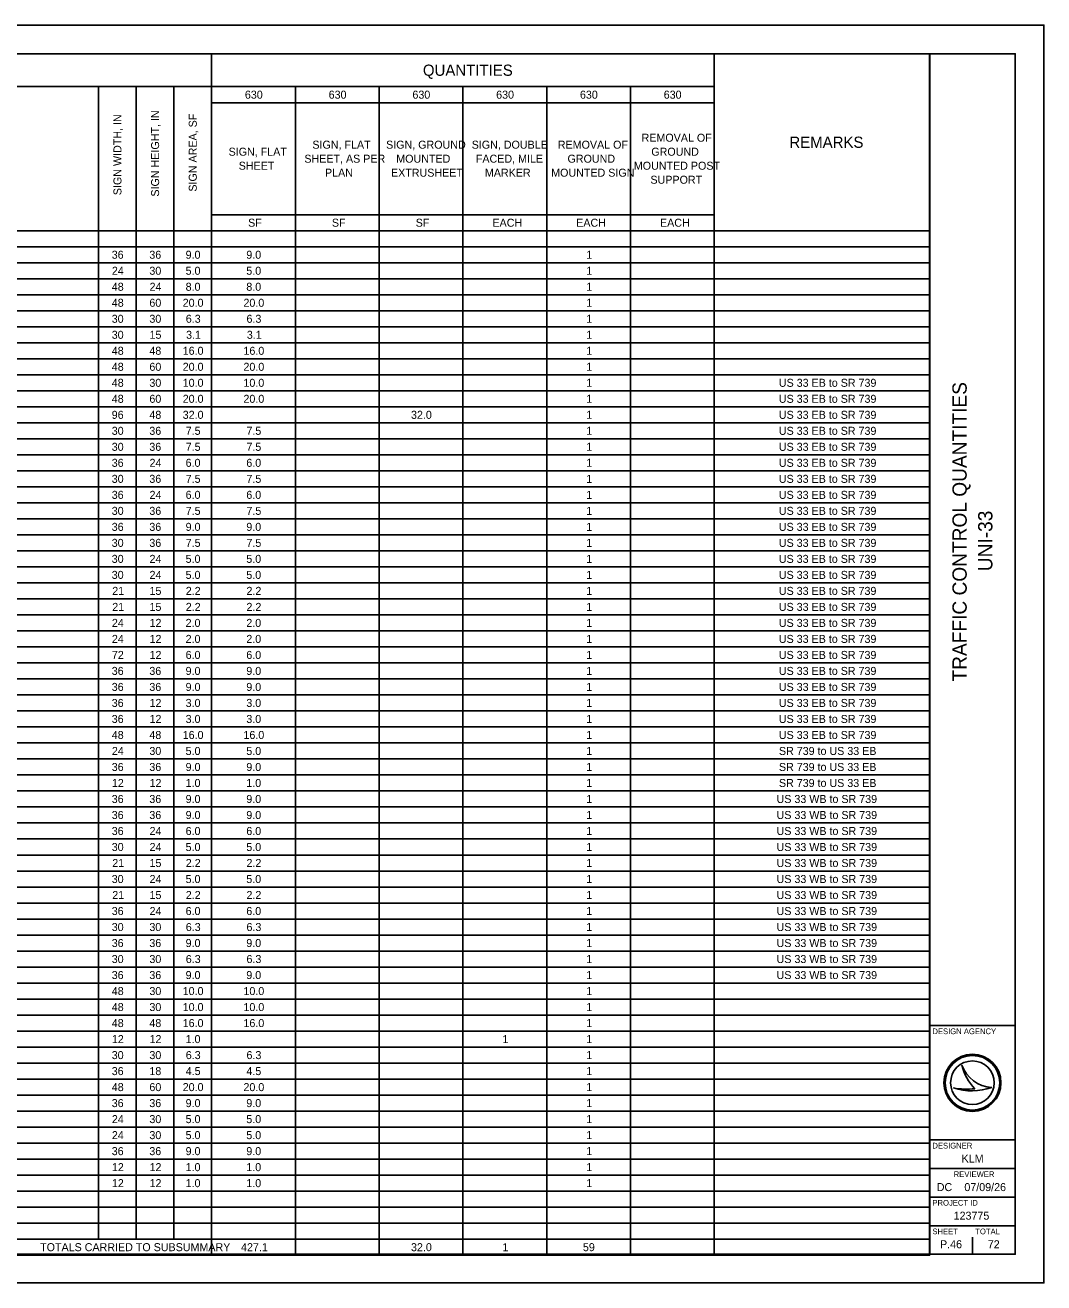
# Model space of a CAD drawing. Extents: x 0 to 34, y 0 to 22.
# Drawn here: x 16.17 to 34, y 0 to 22 of the extents above; entities that cross this region are included whole.
import ezdxf

# ---------------------------------------------------------------- set-up
doc = ezdxf.new("R2010")
doc.units = 0
for name, color, linetype in [('Default', 7, 'Continuous'), ('SH_Border', 7, 'Continuous'), ('SH_Cut_Line', 7, 'Continuous'), ('SH_Data', 7, 'Continuous')]:
    doc.layers.add(name, color=color, linetype=linetype)

msp = doc.modelspace()

# ---------------------------------------------------------------- linework, layer by layer
at = {"layer": 'SH_Border'}
for p, q in [((32, 0.5), (32, 21.5)), ((32, 4.5), (33.5, 4.5)), ((32, 2.5), (33.5, 2.5)), ((32, 2), (33.5, 2)), ((32, 1.5), (33.5, 1.5)), ((32, 1), (33.5, 1))]:
    msp.add_line(p, q, dxfattribs=at)
msp.add_lwpolyline([(1.5, 21.5), (33.5, 21.5), (33.5, 0.5), (1.5, 0.5)], close=True, dxfattribs=at)
at = {"layer": 'SH_Cut_Line'}
msp.add_lwpolyline([(0, 0), (34, 0), (34, 22), (0, 22)], close=True, dxfattribs=at)
at = {"layer": 'SH_Data'}
for p, q in [((1.5, 21.5), (32.004, 21.5)), ((19.436, 21.5), (19.436, 0.484)), ((28.232, 21.5), (28.232, 0.484)), ((32.004, 21.5), (32.004, 0.484)), ((1.5, 20.924), (28.232, 20.924)), ((17.46, 20.924), (17.46, 0.764)), ((18.119, 20.924), (18.119, 0.764)), ((18.778, 20.924), (18.778, 0.764)), ((20.902, 20.924), (20.902, 0.484)), ((22.368, 20.924), (22.368, 0.484)), ((23.834, 20.924), (23.834, 0.484)), ((25.3, 20.924), (25.3, 0.484)), ((26.766, 20.924), (26.766, 0.484)), ((19.436, 20.644), (28.232, 20.644)), ((19.436, 18.684), (28.232, 18.684)), ((1.5, 18.404), (32.004, 18.404)), ((1.5, 18.124), (32.004, 18.124)), ((1.5, 17.844), (32.004, 17.844)), ((1.5, 17.564), (32.004, 17.564)), ((1.5, 17.284), (32.004, 17.284)), ((1.5, 17.004), (32.004, 17.004)), ((1.5, 16.724), (32.004, 16.724)), ((1.5, 16.444), (32.004, 16.444)), ((1.5, 16.164), (32.004, 16.164)), ((1.5, 15.884), (32.004, 15.884)), ((1.5, 15.604), (32.004, 15.604)), ((1.5, 15.324), (32.004, 15.324)), ((1.5, 15.044), (32.004, 15.044)), ((1.5, 14.764), (32.004, 14.764)), ((1.5, 14.484), (32.004, 14.484)), ((1.5, 14.204), (32.004, 14.204)), ((1.5, 13.924), (32.004, 13.924)), ((1.5, 13.644), (32.004, 13.644)), ((1.5, 13.364), (32.004, 13.364)), ((1.5, 13.084), (32.004, 13.084)), ((1.5, 12.804), (32.004, 12.804)), ((1.5, 12.524), (32.004, 12.524)), ((1.5, 12.244), (32.004, 12.244)), ((1.5, 11.964), (32.004, 11.964)), ((1.5, 11.684), (32.004, 11.684)), ((1.5, 11.404), (32.004, 11.404)), ((1.5, 11.124), (32.004, 11.124)), ((1.5, 10.844), (32.004, 10.844)), ((1.5, 10.564), (32.004, 10.564)), ((1.5, 10.284), (32.004, 10.284)), ((1.5, 10.004), (32.004, 10.004)), ((1.5, 9.724), (32.004, 9.724)), ((1.5, 9.444), (32.004, 9.444)), ((1.5, 9.164), (32.004, 9.164)), ((1.5, 8.884), (32.004, 8.884)), ((1.5, 8.604), (32.004, 8.604)), ((1.5, 8.324), (32.004, 8.324)), ((1.5, 8.044), (32.004, 8.044)), ((1.5, 7.764), (32.004, 7.764)), ((1.5, 7.484), (32.004, 7.484)), ((1.5, 7.204), (32.004, 7.204)), ((1.5, 6.924), (32.004, 6.924)), ((1.5, 6.644), (32.004, 6.644)), ((1.5, 6.364), (32.004, 6.364)), ((1.5, 6.084), (32.004, 6.084)), ((1.5, 5.804), (32.004, 5.804)), ((1.5, 5.524), (32.004, 5.524)), ((1.5, 5.244), (32.004, 5.244)), ((1.5, 4.964), (32.004, 4.964)), ((1.5, 4.684), (32.004, 4.684)), ((1.5, 4.404), (32.004, 4.404)), ((1.5, 4.124), (32.004, 4.124)), ((1.5, 3.844), (32.004, 3.844)), ((32.567, 3.81), (32.567, 3.81)), ((1.5, 3.564), (32.004, 3.564)), ((32.417, 3.41), (32.417, 3.41)), ((32.75, 3.5), (32.75, 3.5)), ((33.087, 3.419), (33.087, 3.419)), ((1.5, 3.284), (32.004, 3.284)), ((1.5, 3.004), (32.004, 3.004)), ((1.5, 2.724), (32.004, 2.724)), ((1.5, 2.444), (32.004, 2.444)), ((1.5, 2.164), (32.004, 2.164)), ((1.5, 1.884), (32.004, 1.884)), ((1.5, 1.604), (32.004, 1.604)), ((1.5, 1.324), (32.004, 1.324)), ((1.5, 1.044), (32.004, 1.044)), ((1.5, 0.764), (32.004, 0.764)), ((32.375, 0.675), (32.375, 0.675)), ((32.75, 0.5), (32.75, 0.8)), ((1.5, 0.484), (32.004, 0.484))]:
    msp.add_line(p, q, dxfattribs=at)
for radius in [0.5, 0.477, 0.477, 0.382]:
    msp.add_circle((32.75, 3.5), radius, dxfattribs=at)
for centre, radius, start, end in [((33.116, 3.998), 0.58, 198.9257, 198.9319), ((33.347, 3.97), 0.796, 191.6379, 191.6421), ((33.116, 3.998), 0.58, 198.9319, 267.1657), ((33.347, 3.97), 0.796, 191.6421, 226.0947), ((32.739, 4.37), 1.013, 251.4576, 290.0832), ((32.648, 4.654), 1.266, 259.4964, 259.4995), ((32.739, 4.37), 1.013, 251.4527, 251.4576), ((32.648, 4.654), 1.266, 259.4995, 276.6672)]:
    msp.add_arc(centre, radius, start, end, dxfattribs=at)

# ---------------------------------------------------------------- texts
at = {"layer": 'Default'}
for s, height, p in [('QUANTITIES', 0.196, (23.134, 21.114)), ('630', 0.14, (20.019, 20.714)), ('630', 0.14, (21.485, 20.714)), ('630', 0.14, (22.951, 20.714)), ('630', 0.14, (24.416, 20.714)), ('630', 0.14, (25.882, 20.714)), ('630', 0.14, (27.348, 20.714)), ('REMOVAL OF ', 0.14, (26.961, 19.961)), ('REMARKS', 0.196, (29.547, 19.854)), ('SIGN, FLAT ', 0.14, (19.734, 19.716)), ('SIGN, FLAT ', 0.14, (21.2, 19.839)), ('SIGN, GROUND ', 0.14, (22.49, 19.839)), ('SIGN, DOUBLE ', 0.14, (23.988, 19.839)), ('REMOVAL OF ', 0.14, (25.495, 19.839)), ('GROUND ', 0.14, (27.131, 19.716)), ('SHEET', 0.14, (19.911, 19.471)), ('SHEET, AS PER ', 0.14, (21.06, 19.594)), ('MOUNTED ', 0.14, (22.668, 19.594)), ('FACED, MILE ', 0.14, (24.061, 19.594)), ('GROUND ', 0.14, (25.665, 19.594)), ('MOUNTED POST ', 0.14, (26.825, 19.471)), ('PLAN', 0.14, (21.421, 19.349)), ('EXTRUSHEET', 0.14, (22.576, 19.349)), ('MARKER', 0.14, (24.219, 19.349)), ('MOUNTED SIGN', 0.14, (25.379, 19.349)), ('SUPPORT', 0.14, (27.116, 19.226)), ('SF', 0.14, (20.076, 18.474)), ('SF', 0.14, (21.542, 18.474)), ('SF', 0.14, (23.008, 18.474)), ('EACH', 0.14, (24.351, 18.474)), ('EACH', 0.14, (25.817, 18.474)), ('EACH', 0.14, (27.283, 18.474)), ('36', 0.14, (17.689, 17.914)), ('36', 0.14, (18.347, 17.914)), ('9.0', 0.14, (18.982, 17.914)), ('9.0', 0.14, (20.044, 17.914)), ('1', 0.14, (25.992, 17.914)), ('24', 0.14, (17.692, 17.634)), ('30', 0.14, (18.348, 17.634)), ('5.0', 0.14, (18.982, 17.634)), ('5.0', 0.14, (20.044, 17.634)), ('1', 0.14, (25.992, 17.634)), ('48', 0.14, (17.69, 17.354)), ('24', 0.14, (18.351, 17.354)), ('8.0', 0.14, (18.982, 17.354)), ('8.0', 0.14, (20.044, 17.354)), ('1', 0.14, (25.992, 17.354)), ('48', 0.14, (17.69, 17.074)), ('60', 0.14, (18.348, 17.074)), ('20.0', 0.14, (18.931, 17.074)), ('20.0', 0.14, (19.994, 17.074)), ('1', 0.14, (25.992, 17.074)), ('30', 0.14, (17.689, 16.794)), ('30', 0.14, (18.348, 16.794)), ('6.3', 0.14, (18.985, 16.794)), ('6.3', 0.14, (20.047, 16.794)), ('1', 0.14, (25.992, 16.794)), ('30', 0.14, (17.689, 16.514)), ('15', 0.14, (18.35, 16.514)), ('3.1', 0.14, (18.99, 16.514)), ('3.1', 0.14, (20.053, 16.514)), ('1', 0.14, (25.992, 16.514)), ('48', 0.14, (17.69, 16.234)), ('48', 0.14, (18.348, 16.234)), ('16.0', 0.14, (18.931, 16.234)), ('16.0', 0.14, (19.994, 16.234)), ('1', 0.14, (25.992, 16.234)), ('48', 0.14, (17.69, 15.954)), ('60', 0.14, (18.348, 15.954)), ('20.0', 0.14, (18.931, 15.954)), ('20.0', 0.14, (19.994, 15.954)), ('1', 0.14, (25.992, 15.954)), ('48', 0.14, (17.69, 15.674)), ('30', 0.14, (18.348, 15.674)), ('10.0', 0.14, (18.931, 15.674)), ('10.0', 0.14, (19.994, 15.674)), ('1', 0.14, (25.992, 15.674)), ('US 33 EB to SR 739', 0.14, (29.363, 15.674)), ('48', 0.14, (17.69, 15.394)), ('60', 0.14, (18.348, 15.394)), ('20.0', 0.14, (18.931, 15.394)), ('20.0', 0.14, (19.994, 15.394)), ('1', 0.14, (25.992, 15.394)), ('US 33 EB to SR 739', 0.14, (29.363, 15.394)), ('96', 0.14, (17.689, 15.114)), ('48', 0.14, (18.348, 15.114)), ('32.0', 0.14, (18.931, 15.114)), ('32.0', 0.14, (22.926, 15.114)), ('1', 0.14, (25.992, 15.114)), ('US 33 EB to SR 739', 0.14, (29.363, 15.114)), ('30', 0.14, (17.689, 14.834)), ('36', 0.14, (18.347, 14.834)), ('7.5', 0.14, (18.984, 14.834)), ('7.5', 0.14, (20.046, 14.834)), ('1', 0.14, (25.992, 14.834)), ('US 33 EB to SR 739', 0.14, (29.363, 14.834)), ('30', 0.14, (17.689, 14.554)), ('36', 0.14, (18.347, 14.554)), ('7.5', 0.14, (18.984, 14.554)), ('7.5', 0.14, (20.046, 14.554)), ('1', 0.14, (25.992, 14.554)), ('US 33 EB to SR 739', 0.14, (29.363, 14.554)), ('36', 0.14, (17.689, 14.274)), ('24', 0.14, (18.351, 14.274)), ('6.0', 0.14, (18.982, 14.274)), ('6.0', 0.14, (20.044, 14.274)), ('1', 0.14, (25.992, 14.274)), ('US 33 EB to SR 739', 0.14, (29.363, 14.274)), ('30', 0.14, (17.689, 13.994)), ('36', 0.14, (18.347, 13.994)), ('7.5', 0.14, (18.984, 13.994)), ('7.5', 0.14, (20.046, 13.994)), ('1', 0.14, (25.992, 13.994)), ('US 33 EB to SR 739', 0.14, (29.363, 13.994)), ('36', 0.14, (17.689, 13.714)), ('24', 0.14, (18.351, 13.714)), ('6.0', 0.14, (18.982, 13.714)), ('6.0', 0.14, (20.044, 13.714)), ('1', 0.14, (25.992, 13.714)), ('US 33 EB to SR 739', 0.14, (29.363, 13.714)), ('30', 0.14, (17.689, 13.434)), ('36', 0.14, (18.347, 13.434)), ('7.5', 0.14, (18.984, 13.434)), ('7.5', 0.14, (20.046, 13.434)), ('1', 0.14, (25.992, 13.434)), ('US 33 EB to SR 739', 0.14, (29.363, 13.434)), ('36', 0.14, (17.689, 13.154)), ('36', 0.14, (18.347, 13.154)), ('9.0', 0.14, (18.982, 13.154)), ('9.0', 0.14, (20.044, 13.154)), ('1', 0.14, (25.992, 13.154)), ('US 33 EB to SR 739', 0.14, (29.363, 13.154)), ('30', 0.14, (17.689, 12.874)), ('36', 0.14, (18.347, 12.874)), ('7.5', 0.14, (18.984, 12.874)), ('7.5', 0.14, (20.046, 12.874)), ('1', 0.14, (25.992, 12.874)), ('US 33 EB to SR 739', 0.14, (29.363, 12.874)), ('30', 0.14, (17.689, 12.594)), ('24', 0.14, (18.351, 12.594)), ('5.0', 0.14, (18.982, 12.594)), ('5.0', 0.14, (20.044, 12.594)), ('1', 0.14, (25.992, 12.594)), ('US 33 EB to SR 739', 0.14, (29.363, 12.594)), ('30', 0.14, (17.689, 12.314)), ('24', 0.14, (18.351, 12.314)), ('5.0', 0.14, (18.982, 12.314)), ('5.0', 0.14, (20.044, 12.314)), ('1', 0.14, (25.992, 12.314)), ('US 33 EB to SR 739', 0.14, (29.363, 12.314)), ('21', 0.14, (17.698, 12.034)), ('15', 0.14, (18.35, 12.034)), ('2.2', 0.14, (18.985, 12.034)), ('2.2', 0.14, (20.047, 12.034)), ('1', 0.14, (25.992, 12.034)), ('US 33 EB to SR 739', 0.14, (29.363, 12.034)), ('21', 0.14, (17.698, 11.754)), ('15', 0.14, (18.35, 11.754)), ('2.2', 0.14, (18.985, 11.754)), ('2.2', 0.14, (20.047, 11.754)), ('1', 0.14, (25.992, 11.754)), ('US 33 EB to SR 739', 0.14, (29.363, 11.754)), ('24', 0.14, (17.692, 11.474)), ('12', 0.14, (18.351, 11.474)), ('2.0', 0.14, (18.982, 11.474)), ('2.0', 0.14, (20.044, 11.474)), ('1', 0.14, (25.992, 11.474)), ('US 33 EB to SR 739', 0.14, (29.363, 11.474)), ('24', 0.14, (17.692, 11.194)), ('12', 0.14, (18.351, 11.194)), ('2.0', 0.14, (18.982, 11.194)), ('2.0', 0.14, (20.044, 11.194)), ('1', 0.14, (25.992, 11.194)), ('US 33 EB to SR 739', 0.14, (29.363, 11.194)), ('72', 0.14, (17.692, 10.914)), ('12', 0.14, (18.351, 10.914)), ('6.0', 0.14, (18.982, 10.914)), ('6.0', 0.14, (20.044, 10.914)), ('1', 0.14, (25.992, 10.914)), ('US 33 EB to SR 739', 0.14, (29.363, 10.914)), ('36', 0.14, (17.689, 10.634)), ('36', 0.14, (18.347, 10.634)), ('9.0', 0.14, (18.982, 10.634)), ('9.0', 0.14, (20.044, 10.634)), ('1', 0.14, (25.992, 10.634)), ('US 33 EB to SR 739', 0.14, (29.363, 10.634)), ('36', 0.14, (17.689, 10.354)), ('36', 0.14, (18.347, 10.354)), ('9.0', 0.14, (18.982, 10.354)), ('9.0', 0.14, (20.044, 10.354)), ('1', 0.14, (25.992, 10.354)), ('US 33 EB to SR 739', 0.14, (29.363, 10.354)), ('36', 0.14, (17.689, 10.074)), ('12', 0.14, (18.351, 10.074)), ('3.0', 0.14, (18.982, 10.074)), ('3.0', 0.14, (20.044, 10.074)), ('1', 0.14, (25.992, 10.074)), ('US 33 EB to SR 739', 0.14, (29.363, 10.074)), ('36', 0.14, (17.689, 9.794)), ('12', 0.14, (18.351, 9.794)), ('3.0', 0.14, (18.982, 9.794)), ('3.0', 0.14, (20.044, 9.794)), ('1', 0.14, (25.992, 9.794)), ('US 33 EB to SR 739', 0.14, (29.363, 9.794)), ('48', 0.14, (17.69, 9.514)), ('48', 0.14, (18.348, 9.514)), ('16.0', 0.14, (18.931, 9.514)), ('16.0', 0.14, (19.994, 9.514)), ('1', 0.14, (25.992, 9.514)), ('US 33 EB to SR 739', 0.14, (29.363, 9.514)), ('24', 0.14, (17.692, 9.234)), ('30', 0.14, (18.348, 9.234)), ('5.0', 0.14, (18.982, 9.234)), ('5.0', 0.14, (20.044, 9.234)), ('1', 0.14, (25.992, 9.234)), ('SR 739 to US 33 EB', 0.14, (29.364, 9.234)), ('36', 0.14, (17.689, 8.954)), ('36', 0.14, (18.347, 8.954)), ('9.0', 0.14, (18.982, 8.954)), ('9.0', 0.14, (20.044, 8.954)), ('1', 0.14, (25.992, 8.954)), ('SR 739 to US 33 EB', 0.14, (29.364, 8.954)), ('12', 0.14, (17.692, 8.674)), ('12', 0.14, (18.351, 8.674)), ('1.0', 0.14, (18.982, 8.674)), ('1.0', 0.14, (20.044, 8.674)), ('1', 0.14, (25.992, 8.674)), ('SR 739 to US 33 EB', 0.14, (29.364, 8.674)), ('36', 0.14, (17.689, 8.394)), ('36', 0.14, (18.347, 8.394)), ('9.0', 0.14, (18.982, 8.394)), ('9.0', 0.14, (20.044, 8.394)), ('1', 0.14, (25.992, 8.394)), ('US 33 WB to SR 739', 0.14, (29.323, 8.394)), ('36', 0.14, (17.689, 8.114)), ('36', 0.14, (18.347, 8.114)), ('9.0', 0.14, (18.982, 8.114)), ('9.0', 0.14, (20.044, 8.114)), ('1', 0.14, (25.992, 8.114)), ('US 33 WB to SR 739', 0.14, (29.323, 8.114)), ('36', 0.14, (17.689, 7.834)), ('24', 0.14, (18.351, 7.834)), ('6.0', 0.14, (18.982, 7.834)), ('6.0', 0.14, (20.044, 7.834)), ('1', 0.14, (25.992, 7.834)), ('US 33 WB to SR 739', 0.14, (29.323, 7.834)), ('30', 0.14, (17.689, 7.554)), ('24', 0.14, (18.351, 7.554)), ('5.0', 0.14, (18.982, 7.554)), ('5.0', 0.14, (20.044, 7.554)), ('1', 0.14, (25.992, 7.554)), ('US 33 WB to SR 739', 0.14, (29.323, 7.554)), ('21', 0.14, (17.698, 7.274)), ('15', 0.14, (18.35, 7.274)), ('2.2', 0.14, (18.985, 7.274)), ('2.2', 0.14, (20.047, 7.274)), ('1', 0.14, (25.992, 7.274)), ('US 33 WB to SR 739', 0.14, (29.323, 7.274)), ('30', 0.14, (17.689, 6.994)), ('24', 0.14, (18.351, 6.994)), ('5.0', 0.14, (18.982, 6.994)), ('5.0', 0.14, (20.044, 6.994)), ('1', 0.14, (25.992, 6.994)), ('US 33 WB to SR 739', 0.14, (29.323, 6.994)), ('21', 0.14, (17.698, 6.714)), ('15', 0.14, (18.35, 6.714)), ('2.2', 0.14, (18.985, 6.714)), ('2.2', 0.14, (20.047, 6.714)), ('1', 0.14, (25.992, 6.714)), ('US 33 WB to SR 739', 0.14, (29.323, 6.714)), ('36', 0.14, (17.689, 6.434)), ('24', 0.14, (18.351, 6.434)), ('6.0', 0.14, (18.982, 6.434)), ('6.0', 0.14, (20.044, 6.434)), ('1', 0.14, (25.992, 6.434)), ('US 33 WB to SR 739', 0.14, (29.323, 6.434)), ('30', 0.14, (17.689, 6.154)), ('30', 0.14, (18.348, 6.154)), ('6.3', 0.14, (18.985, 6.154)), ('6.3', 0.14, (20.047, 6.154)), ('1', 0.14, (25.992, 6.154)), ('US 33 WB to SR 739', 0.14, (29.323, 6.154)), ('36', 0.14, (17.689, 5.874)), ('36', 0.14, (18.347, 5.874)), ('9.0', 0.14, (18.982, 5.874)), ('9.0', 0.14, (20.044, 5.874)), ('1', 0.14, (25.992, 5.874)), ('US 33 WB to SR 739', 0.14, (29.323, 5.874)), ('30', 0.14, (17.689, 5.594)), ('30', 0.14, (18.348, 5.594)), ('6.3', 0.14, (18.985, 5.594)), ('6.3', 0.14, (20.047, 5.594)), ('1', 0.14, (25.992, 5.594)), ('US 33 WB to SR 739', 0.14, (29.323, 5.594)), ('36', 0.14, (17.689, 5.314)), ('36', 0.14, (18.347, 5.314)), ('9.0', 0.14, (18.982, 5.314)), ('9.0', 0.14, (20.044, 5.314)), ('1', 0.14, (25.992, 5.314)), ('US 33 WB to SR 739', 0.14, (29.323, 5.314)), ('48', 0.14, (17.69, 5.034)), ('30', 0.14, (18.348, 5.034)), ('10.0', 0.14, (18.931, 5.034)), ('10.0', 0.14, (19.994, 5.034)), ('1', 0.14, (25.992, 5.034)), ('48', 0.14, (17.69, 4.754)), ('30', 0.14, (18.348, 4.754)), ('10.0', 0.14, (18.931, 4.754)), ('10.0', 0.14, (19.994, 4.754)), ('1', 0.14, (25.992, 4.754)), ('48', 0.14, (17.69, 4.474)), ('48', 0.14, (18.348, 4.474)), ('16.0', 0.14, (18.931, 4.474)), ('16.0', 0.14, (19.994, 4.474)), ('1', 0.14, (25.992, 4.474)), ('12', 0.14, (17.692, 4.194)), ('12', 0.14, (18.351, 4.194)), ('1.0', 0.14, (18.982, 4.194)), ('1', 0.14, (24.526, 4.194)), ('1', 0.14, (25.992, 4.194)), ('30', 0.14, (17.689, 3.914)), ('30', 0.14, (18.348, 3.914)), ('6.3', 0.14, (18.985, 3.914)), ('6.3', 0.14, (20.047, 3.914)), ('1', 0.14, (25.992, 3.914)), ('36', 0.14, (17.689, 3.634)), ('18', 0.14, (18.348, 3.634)), ('4.5', 0.14, (18.984, 3.634)), ('4.5', 0.14, (20.046, 3.634)), ('1', 0.14, (25.992, 3.634)), ('48', 0.14, (17.69, 3.354)), ('60', 0.14, (18.348, 3.354)), ('20.0', 0.14, (18.931, 3.354)), ('20.0', 0.14, (19.994, 3.354)), ('1', 0.14, (25.992, 3.354)), ('36', 0.14, (17.689, 3.074)), ('36', 0.14, (18.347, 3.074)), ('9.0', 0.14, (18.982, 3.074)), ('9.0', 0.14, (20.044, 3.074)), ('1', 0.14, (25.992, 3.074)), ('24', 0.14, (17.692, 2.794)), ('30', 0.14, (18.348, 2.794)), ('5.0', 0.14, (18.982, 2.794)), ('5.0', 0.14, (20.044, 2.794)), ('1', 0.14, (25.992, 2.794)), ('24', 0.14, (17.692, 2.514)), ('30', 0.14, (18.348, 2.514)), ('5.0', 0.14, (18.982, 2.514)), ('5.0', 0.14, (20.044, 2.514)), ('1', 0.14, (25.992, 2.514)), ('36', 0.14, (17.689, 2.234)), ('36', 0.14, (18.347, 2.234)), ('9.0', 0.14, (18.982, 2.234)), ('9.0', 0.14, (20.044, 2.234)), ('1', 0.14, (25.992, 2.234)), ('12', 0.14, (17.692, 1.954)), ('12', 0.14, (18.351, 1.954)), ('1.0', 0.14, (18.982, 1.954)), ('1.0', 0.14, (20.044, 1.954)), ('1', 0.14, (25.992, 1.954)), ('12', 0.14, (17.692, 1.674)), ('12', 0.14, (18.351, 1.674)), ('1.0', 0.14, (18.982, 1.674)), ('1.0', 0.14, (20.044, 1.674)), ('1', 0.14, (25.992, 1.674)), ('TOTALS CARRIED TO SUBSUMMARY', 0.14, (16.436, 0.554)), ('427.1', 0.14, (19.952, 0.554)), ('32.0', 0.14, (22.926, 0.554)), ('1', 0.14, (24.526, 0.554)), ('59', 0.14, (25.934, 0.554))]:
    msp.add_text(s, height=height, dxfattribs=at).set_placement(p)
for s, p in [('SIGN HEIGHT, IN', (18.518, 19.001)), ('SIGN WIDTH, IN', (17.859, 19.026)), ('SIGN AREA, SF', (19.177, 19.088))]:
    msp.add_text(s, height=0.14, rotation=90, dxfattribs=at).set_placement(p)
at = {"layer": 'SH_Data'}
for s, p in [('TRAFFIC CONTROL QUANTITIES', (32.65, 10.519)), ('UNI-33', (33.1, 12.449))]:
    msp.add_text(s, height=0.25, rotation=90, dxfattribs=at).set_placement(p)
for s, height, p in [('DESIGN AGENCY', 0.1, (32.05, 4.35)), ('DESIGNER', 0.1, (32.05, 2.35)), ('KLM', 0.14, (32.561, 2.105)), ('REVIEWER', 0.1, (32.422, 1.85)), ('DC', 0.14, (32.126, 1.605)), ('07/09/26', 0.14, (32.609, 1.605)), ('PROJECT ID', 0.1, (32.05, 1.35)), ('123775', 0.14, (32.421, 1.105)), ('SHEET', 0.1, (32.05, 0.85)), ('TOTAL', 0.1, (32.8, 0.85)), ('P.46', 0.14, (32.183, 0.605)), ('72', 0.14, (33.019, 0.605))]:
    msp.add_text(s, height=height, dxfattribs=at).set_placement(p)

doc.saveas('drawing.dxf')
